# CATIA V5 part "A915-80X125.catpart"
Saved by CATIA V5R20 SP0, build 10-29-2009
Part number: A915-80X125
Source: Unknown
Property "A": "0.000"
Property "ARTICLENO": "A915-80X125"
Property "BOMINFO": "A915-80X125"
Property "CODE": "A915-80X125"
Property "CREATOR": "CADENAS GmbH"
Property "D": "13.500"
Property "D1": "20.000"
Property "FORM": "B"
Property "L": "125.000"
Property "L1": "25.000"
Property "L2": "75.000"
Property "LINA": "A915-80X125"
Property "NB": "A915-80X125"
Property "NBSYN": "$CODE."
Property "NN": "A915"
Property "NT": "VDI 3357 Wear Plates, steel"
Property "SCREW": "M12x25"
Property "SUPPLIER": "CF"
Property "T": "13.000"
Property "W": "80.000"
Bounding box of the stored display mesh (mm): x 0 to 20, y 0 to 125, z -40 to 40
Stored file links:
  C:\Users\borellobunino\Desktop\3D X SITO CF\A915\GSB_OILLESS_G22501080125\CATIAV5\A915-80X125.catpart
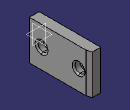
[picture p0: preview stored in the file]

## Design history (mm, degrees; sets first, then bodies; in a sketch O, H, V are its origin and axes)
Body1 "Geometry.1" (main body)
  Solid1 "A915-80X125.catpart": solid without history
